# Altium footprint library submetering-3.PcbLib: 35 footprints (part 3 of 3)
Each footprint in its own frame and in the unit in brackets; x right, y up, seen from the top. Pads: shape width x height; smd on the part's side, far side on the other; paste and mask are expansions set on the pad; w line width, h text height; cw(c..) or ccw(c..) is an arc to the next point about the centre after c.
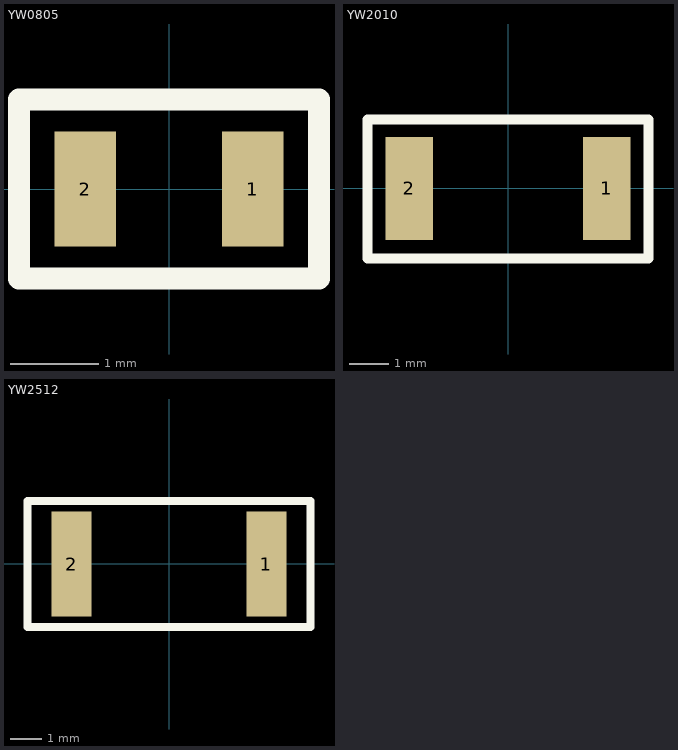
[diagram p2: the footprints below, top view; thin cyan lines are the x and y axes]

## YW0805 [mm]
pads (2):
  rect 0.7x1.3 smd: 1(0.946,0) 2(-0.954,0)
TopOverlay:
  lines w0.254: -1.706,-1.016 -1.706,1.016 1.698,1.016 1.698,-1.016 -1.706,-1.016

## YW2010 [mm]
pads (2):
  rect 1.2x2.6 smd: 1(2.5,0) 2(-2.5,0)
TopOverlay:
  lines w0.254: -3.556,-1.778 3.556,-1.778 3.556,1.753 -3.556,1.753 -3.556,-1.778

## YW2512 [mm]
pads (2):
  rect 1.3x3.4 smd: 1(3.15,-0.011) 2(-3.15,-0.011)
TopOverlay:
  lines w0.254: -4.572,-2.043 4.572,-2.043 4.572,2.021 -4.572,2.021 -4.572,-2.043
